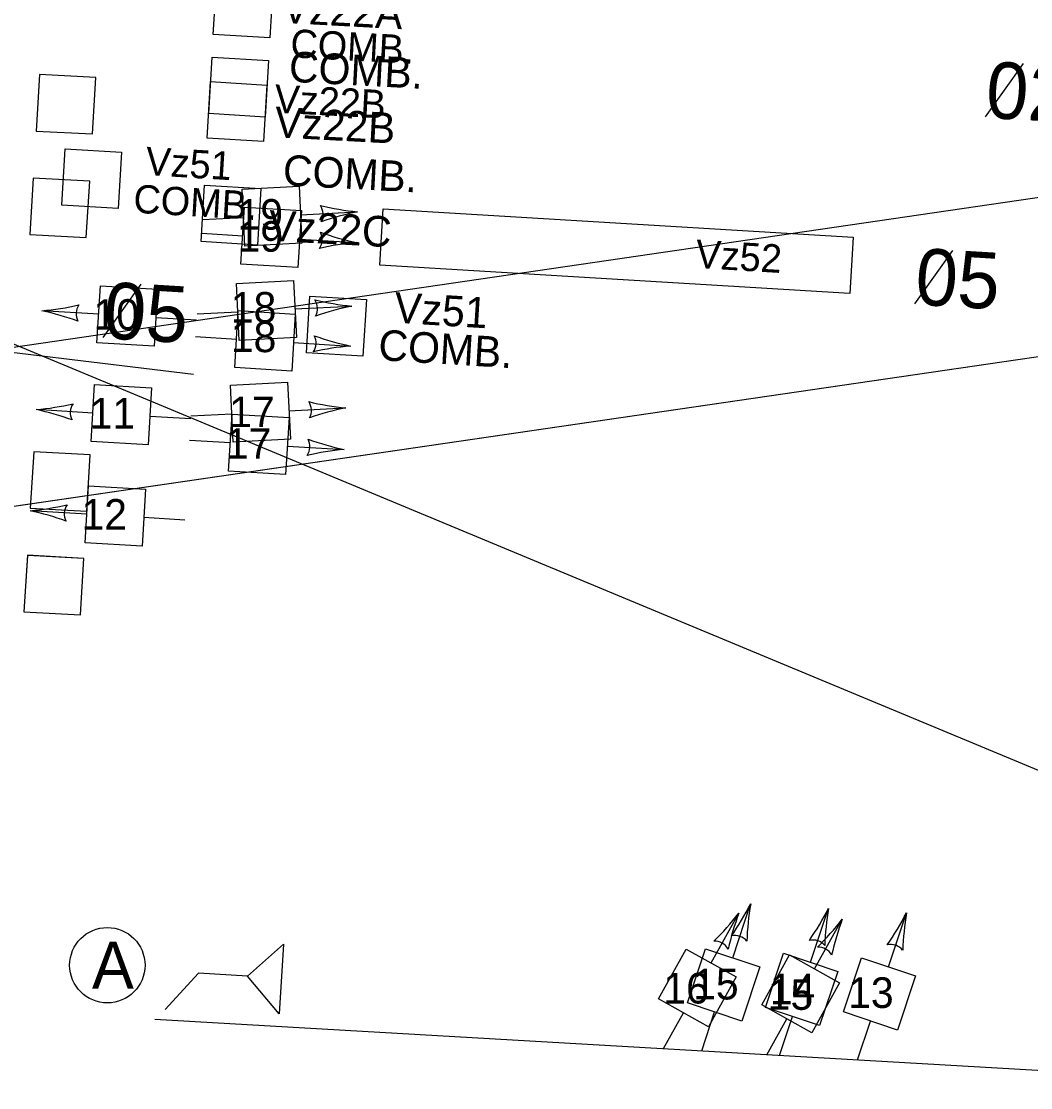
# Model space of a CAD drawing. Extents: x 647787 to 668496, y 640478 to 654412.
# Drawn here: x 661989.9 to 662097, y 647231.7 to 647344.8 of the extents above; entities that cross this region are included whole.
import ezdxf

# ---------------------------------------------------------------- set-up
doc = ezdxf.new("R2010")
doc.units = 0
for name, color, linetype in [('Default', 7, 'Continuous'), ('TEMP_DETECTION ZONE_Stage 2', 7, 'Continuous'), ('TEMP_DETECTION ZONE_STAGE 3', 7, 'Continuous'), ('TEMP_DETECTION_ZONE_STAGE 4', 7, 'Continuous'), ('TEMP_DETECTION_ZONE_STAGE 5', 7, 'Continuous'), ('TEMP_SIGNAL_HEAD_STAGE 2', 7, 'Continuous'), ('TEMP_SIGNAL_HEAD_Stage 3', 7, 'Continuous'), ('TEMP_SIGNAL_HEAD_STAGE4', 7, 'Continuous'), ('TEMP_SIGNAL_POLES_STAGE 1B', 7, 'Continuous'), ('TEMP_SIGNAL_POLES_STAGE 3', 7, 'Continuous'), ('TEMP_SIGNAL_POLES_STAGE 4', 7, 'Continuous'), ('TEXT_TEMP_SIGNAL_POLES_STAGE 2', 7, 'Continuous'), ('TEXT_TEMP_SIGNAL_POLES_STAGE 3', 7, 'Continuous'), ('TEXT_TEMP_SIGNAL_POLES_STAGE 4', 7, 'Continuous')]:
    doc.layers.add(name, color=color, linetype=linetype)

msp = doc.modelspace()

# ---------------------------------------------------------------- linework, layer by layer
at = {"layer": 'Default'}
for p, q in [((662092.24, 647334.7), (662096.28, 647340.36)), ((662084.74, 647314.88), (662088.79, 647320.54)), ((661998.56, 647311.3), (662002.6, 647316.96))]:
    msp.add_line(p, q, dxfattribs=at)
for points in [[(662193.11, 647333.04), (662139.14, 647248.2), (661974.83, 647316.48)], [(662136.44, 647331.77), (661882.02, 647294.61), (661114.4, 647320.89)], [(662008.15, 647307.38), (661891.05, 647321.5)], [(662008.15, 647307.38), (661891.05, 647321.5)], [(662008.15, 647307.38), (661891.05, 647321.5)], [(662108.29, 647310.77), (661853.87, 647273.61), (661086.25, 647299.89)], [(662108.29, 647310.77), (661888.55, 647278.68)], [(662108.29, 647310.77), (661888.55, 647278.68)]]:
    msp.add_lwpolyline(points, dxfattribs=at)
at = {"layer": 'TEMP_DETECTION ZONE_Stage 2'}
msp.add_lwpolyline([(662027.94, 647318.97), (662028.3, 647324.96), (662078.21, 647321.95), (662077.85, 647315.96)], close=True, dxfattribs=at)
at = {"layer": 'TEMP_DETECTION ZONE_STAGE 3'}
for points in [[(661991.81, 647339.19), (661991.45, 647333.2), (661997.44, 647332.89), (661997.8, 647338.88)], [(661991.81, 647339.19), (661991.45, 647333.2), (661997.44, 647332.89), (661997.8, 647338.88)], [(661991.81, 647339.19), (661991.45, 647333.2), (661997.44, 647332.89), (661997.8, 647338.88)], [(661991.81, 647339.19), (661991.45, 647333.2), (661997.44, 647332.89), (661997.8, 647338.88)], [(661991.15, 647328.21), (661990.78, 647322.22), (661996.78, 647321.91), (661997.14, 647327.9)], [(661991.15, 647328.21), (661990.78, 647322.22), (661996.78, 647321.91), (661997.14, 647327.9)], [(661991.15, 647328.21), (661990.78, 647322.22), (661996.78, 647321.91), (661997.14, 647327.9)], [(661991.15, 647328.21), (661990.79, 647322.22), (661996.78, 647321.91), (661997.14, 647327.9)]]:
    msp.add_lwpolyline(points, close=True, dxfattribs=at)
at = {"layer": 'TEMP_DETECTION_ZONE_STAGE 4'}
for points in [[(661991.19, 647299.15), (661990.82, 647293.17), (661996.82, 647292.85), (661997.18, 647298.84)], [(661991.19, 647299.15), (661990.82, 647293.17), (661996.82, 647292.85), (661997.18, 647298.84)], [(661991.19, 647299.15), (661990.82, 647293.17), (661996.82, 647292.85), (661997.18, 647298.84)], [(661991.19, 647299.16), (661990.83, 647293.17), (661996.82, 647292.86), (661997.18, 647298.84)], [(661990.53, 647288.18), (661990.16, 647282.19), (661996.16, 647281.88), (661996.52, 647287.86)], [(661990.52, 647288.17), (661990.16, 647282.19), (661996.15, 647281.87), (661996.52, 647287.86)], [(661990.52, 647288.17), (661990.16, 647282.19), (661996.15, 647281.87), (661996.52, 647287.86)], [(661990.52, 647288.17), (661990.16, 647282.19), (661996.15, 647281.87), (661996.52, 647287.86)]]:
    msp.add_lwpolyline(points, close=True, dxfattribs=at)
at = {"layer": 'TEMP_DETECTION_ZONE_STAGE 5'}
for points in [[(662015.77, 647334.69), (662009.78, 647335.05), (662010.14, 647341.04), (662016.13, 647340.68)], [(662000.16, 647324.97), (661994.17, 647325.33), (661994.53, 647331.32), (662000.52, 647330.96)]]:
    msp.add_lwpolyline(points, close=True, dxfattribs=at)
at = {"layer": 'TEMP_SIGNAL_HEAD_STAGE 2'}
for p, q in [((661998.1, 647313.76), (661992.07, 647314.12)), ((662008.49, 647313.13), (662004.15, 647313.39)), ((661997.47, 647303.28), (661991.44, 647303.64)), ((662007.86, 647302.65), (662003.53, 647302.91)), ((661996.84, 647292.55), (661990.81, 647292.91)), ((662007.23, 647291.92), (662002.89, 647292.18)), ((662008.69, 647243.84), (662005.16, 647239.99))]:
    msp.add_line(p, q, dxfattribs=at)
for points in [[(662004.33, 647316.42), (662003.97, 647310.37), (661997.91, 647310.73), (661998.28, 647316.79)], [(662003.71, 647305.94), (662003.34, 647299.89), (661997.29, 647300.25), (661997.66, 647306.3)], [(662003.07, 647295.21), (662002.7, 647289.15), (661996.65, 647289.52), (661997.02, 647295.57)]]:
    msp.add_lwpolyline(points, close=True, dxfattribs=at)
msp.add_lwpolyline([(662013.9, 647243.53), (662017.71, 647246.91), (662017.26, 647239.54), (662013.9, 647243.53), (662008.69, 647243.84)], dxfattribs=at)
for centre, radius, start, end in [((661989.42, 647343.48), 29.47, 275.1562, 282.8943), ((661985.91, 647285.3), 29.47, 70.2014, 77.9395), ((661997.32, 647313.81), 1.63, 144.7005, 208.3952), ((661988.8, 647332.99), 29.47, 275.1562, 282.8943), ((661985.29, 647274.82), 29.47, 70.2014, 77.9395), ((661996.7, 647303.32), 1.63, 144.7005, 208.3952), ((661988.16, 647322.26), 29.47, 275.1562, 282.8943), ((661996.06, 647292.59), 1.63, 144.7005, 208.3952), ((661984.65, 647264.09), 29.47, 70.2014, 77.9395)]:
    msp.add_arc(centre, radius, start, end, dxfattribs=at)
at = {"layer": 'TEMP_SIGNAL_HEAD_Stage 3'}
for p, q in [((662009.12, 647323.8), (662013.46, 647324.02)), ((662019.52, 647324.32), (662025.55, 647324.63)), ((662008.53, 647313.79), (662012.87, 647314.01)), ((662018.92, 647314.32), (662024.96, 647314.62)), ((662018.28, 647303.52), (662024.31, 647303.83)), ((662007.88, 647302.99), (662012.23, 647303.21)), ((662063.12, 647244.93), (662066.05, 647250.21)), ((662074.1, 647244.29), (662077.03, 647249.57)), ((662008.69, 647243.84), (662005.16, 647239.99)), ((662058.06, 647235.83), (662060.17, 647239.63)), ((662069.04, 647235.19), (662071.15, 647238.99))]:
    msp.add_line(p, q, dxfattribs=at)
for points in [[(662013.62, 647320.99), (662013.31, 647327.05), (662019.36, 647327.35), (662019.67, 647321.3)], [(662013.02, 647310.98), (662012.71, 647317.04), (662018.77, 647317.35), (662019.08, 647311.29)], [(662012.38, 647300.18), (662012.07, 647306.24), (662018.13, 647306.55), (662018.44, 647300.49)], [(662062.82, 647238.16), (662057.52, 647241.1), (662060.47, 647246.4), (662065.77, 647243.46)], [(662073.8, 647237.52), (662068.5, 647240.47), (662071.45, 647245.77), (662076.75, 647242.82)]]:
    msp.add_lwpolyline(points, close=True, dxfattribs=at)
msp.add_lwpolyline([(662013.9, 647243.53), (662017.71, 647246.91), (662017.26, 647239.54), (662013.9, 647243.53), (662008.69, 647243.84)], dxfattribs=at)
for centre, radius, start, end in [((662020.29, 647324.36), 1.63, 331.0639, 34.7585), ((662028.48, 647353.96), 29.47, 256.5647, 264.3029), ((662031.44, 647295.75), 29.47, 101.5195, 109.2576), ((662019.7, 647314.36), 1.63, 331.0639, 34.7585), ((662027.88, 647343.95), 29.47, 256.5647, 264.3029), ((662030.84, 647285.75), 29.47, 101.5195, 109.2576), ((662019.05, 647303.56), 1.63, 331.0639, 34.7585), ((662027.24, 647333.15), 29.47, 256.5647, 264.3029), ((662030.2, 647274.95), 29.47, 101.5195, 109.2576), ((662042.73, 647268.22), 29.47, 314.5817, 322.3198), ((662093.67, 647239.9), 29.47, 159.5365, 167.2746), ((662053.71, 647267.59), 29.47, 314.5817, 322.3198), ((662104.65, 647239.27), 29.47, 159.5365, 167.2746), ((662063.49, 647245.61), 1.63, 29.0808, 92.7755), ((662074.48, 647244.97), 1.63, 29.0808, 92.7755)]:
    msp.add_arc(centre, radius, start, end, dxfattribs=at)
at = {"layer": 'TEMP_SIGNAL_HEAD_STAGE4'}
for p, q in [((662009.04, 647322.37), (662013.38, 647322.1)), ((662019.43, 647321.74), (662025.46, 647321.37)), ((662008.38, 647311.39), (662012.72, 647311.12)), ((662018.78, 647310.76), (662024.8, 647310.39)), ((662007.73, 647300.4), (662012.07, 647300.14)), ((662018.12, 647299.78), (662024.15, 647299.41)), ((662065.4, 647245.47), (662067.31, 647251.2)), ((662073.67, 647244.99), (662075.59, 647250.72)), ((662081.95, 647244.51), (662083.86, 647250.24)), ((662008.69, 647243.84), (662005.16, 647239.99)), ((662062.11, 647235.6), (662063.48, 647239.72)), ((662070.38, 647235.12), (662071.75, 647239.24)), ((662078.65, 647234.64), (662080.03, 647238.76))]:
    msp.add_line(p, q, dxfattribs=at)
for points in [[(662013.19, 647319.08), (662013.56, 647325.13), (662019.61, 647324.76), (662019.25, 647318.71)], [(662012.54, 647308.1), (662012.91, 647314.15), (662018.96, 647313.78), (662018.59, 647307.73)], [(662011.89, 647297.12), (662012.25, 647303.17), (662018.3, 647302.8), (662017.94, 647296.75)], [(662066.36, 647238.76), (662060.6, 647240.68), (662062.52, 647246.43), (662068.28, 647244.51)], [(662074.63, 647238.28), (662068.88, 647240.2), (662070.8, 647245.95), (662076.55, 647244.03)], [(662082.9, 647237.8), (662077.15, 647239.72), (662079.07, 647245.47), (662084.82, 647243.55)]]:
    msp.add_lwpolyline(points, close=True, dxfattribs=at)
msp.add_lwpolyline([(662013.9, 647243.53), (662017.71, 647246.91), (662017.26, 647239.54), (662013.9, 647243.53), (662008.69, 647243.84)], dxfattribs=at)
for centre, radius, start, end in [((662020.2, 647321.69), 1.63, 324.6952, 28.3898), ((662031.62, 647350.19), 29.47, 250.1961, 257.9342), ((662028.1, 647292.02), 29.47, 95.1508, 102.8889), ((662019.55, 647310.71), 1.63, 324.6952, 28.3898), ((662027.45, 647281.04), 29.47, 95.1508, 102.8889), ((662030.97, 647339.21), 29.47, 250.1961, 257.9342), ((662018.89, 647299.73), 1.63, 324.6952, 28.3898), ((662030.31, 647328.23), 29.47, 250.1961, 257.9342), ((662026.8, 647270.06), 29.47, 95.1508, 102.8889), ((662041.07, 647264.61), 29.47, 325.2014, 332.9395), ((662096.35, 647246.16), 29.47, 170.1562, 177.8943), ((662049.34, 647264.13), 29.47, 325.2014, 332.9395), ((662104.62, 647245.68), 29.47, 170.1562, 177.8943), ((662057.61, 647263.65), 29.47, 325.2014, 332.9395), ((662112.9, 647245.2), 29.47, 170.1562, 177.8943), ((662065.65, 647246.2), 1.63, 39.7005, 103.3952), ((662073.92, 647245.73), 1.63, 39.7005, 103.3952), ((662082.19, 647245.25), 1.63, 39.7005, 103.3952)]:
    msp.add_arc(centre, radius, start, end, dxfattribs=at)
at = {"layer": 'TEMP_SIGNAL_POLES_STAGE 1B'}
for points in [[(662016.25, 647343.08), (662010.26, 647343.44), (662010.62, 647349.43), (662016.61, 647349.06)], [(662015.58, 647332.09), (662009.6, 647332.46), (662009.96, 647338.45), (662015.95, 647338.08)], [(662014.95, 647321.11), (662008.96, 647321.47), (662009.32, 647327.46), (662015.31, 647327.1)], [(662026.15, 647309.32), (662020.16, 647309.68), (662020.52, 647315.67), (662026.51, 647315.31)]]:
    msp.add_lwpolyline(points, close=True, dxfattribs=at)
at = {"layer": 'TEMP_SIGNAL_POLES_STAGE 3'}
msp.add_line((662004.07, 647238.96), (662129.5, 647231.69), dxfattribs=at)
at = {"layer": 'TEMP_SIGNAL_POLES_STAGE 4'}
msp.add_line((662004.07, 647238.96), (662129.5, 647231.69), dxfattribs=at)
at = {"layer": 'TEXT_TEMP_SIGNAL_POLES_STAGE 2'}
msp.add_circle((661999.01, 647244.68), 4, dxfattribs=at)
at = {"layer": 'TEXT_TEMP_SIGNAL_POLES_STAGE 3'}
msp.add_circle((661999.01, 647244.68), 4, dxfattribs=at)
at = {"layer": 'TEXT_TEMP_SIGNAL_POLES_STAGE 4'}
msp.add_circle((661999.01, 647244.68), 4, dxfattribs=at)

# ---------------------------------------------------------------- texts
at = {"layer": 'Default'}
for s, p in [('02', (662092.17, 647334.62)), ('05', (662084.68, 647314.8)), ('05', (661998.5, 647311.22))]:
    msp.add_text(s, height=6, rotation=356.6181, dxfattribs=at).set_placement(p)
at = {"layer": 'TEMP_DETECTION ZONE_Stage 2'}
msp.add_text('Vz52', height=3, rotation=356.5267, dxfattribs=at).set_placement((662061.4, 647318.69))
at = {"layer": 'TEMP_DETECTION_ZONE_STAGE 5'}
for s, rotation, p in [('COMB.', 356.9362, (662018.39, 647341.03)), ('Vz22B', 356.9362, (662016.69, 647335.16)), ('Vz51', 356.5267, (662003, 647328.54)), ('COMB.', 356.5267, (662001.71, 647324.55))]:
    msp.add_text(s, height=3, rotation=rotation, dxfattribs=at).set_placement(p)
at = {"layer": 'TEMP_SIGNAL_POLES_STAGE 1B'}
for s, rotation, p in [('Vz22A', 356.9362, (662017.5, 647344.69)), ('COMB.', 356.9362, (662018.23, 647338.44)), ('Vz22B', 356.9362, (662016.71, 647332.55)), ('COMB.', 356.9362, (662017.59, 647327.45)), ('Vz22C', 356.9362, (662016.07, 647321.57)), ('Vz51', 356.5267, (662029.4, 647312.87)), ('COMB.', 356.5267, (662027.72, 647308.9))]:
    msp.add_text(s, height=3.25, rotation=rotation, dxfattribs=at).set_placement(p)
at = {"layer": 'TEXT_TEMP_SIGNAL_POLES_STAGE 2'}
for s, height, p in [('10', 3.25, (661997.54, 647312.11)), ('11', 3.25, (661997.13, 647301.63)), ('12', 3.25, (661996.26, 647290.9)), ('A', 5, (661997.37, 647242.18))]:
    msp.add_text(s, height=height, dxfattribs=at).set_placement(p)
at = {"layer": 'TEXT_TEMP_SIGNAL_POLES_STAGE 3'}
for s, height, p in [('19', 3.25, (662012.83, 647322.73)), ('18', 3.25, (662012.12, 647312.87)), ('17', 3.25, (662011.95, 647301.78)), ('A', 5, (661997.37, 647242.18)), ('16', 3.25, (662058.04, 647240.62)), ('15', 3.25, (662069.12, 647239.95))]:
    msp.add_text(s, height=height, dxfattribs=at).set_placement(p)
at = {"layer": 'TEXT_TEMP_SIGNAL_POLES_STAGE 4'}
for s, height, p in [('19', 3.25, (662012.83, 647320.4)), ('18', 3.25, (662012.12, 647309.74)), ('17', 3.25, (662011.59, 647298.42)), ('A', 5, (661997.37, 647242.18)), ('15', 3.25, (662061.2, 647241.05)), ('14', 3.25, (662069.34, 647240.54)), ('13', 3.25, (662077.66, 647240.15))]:
    msp.add_text(s, height=height, dxfattribs=at).set_placement(p)

doc.saveas('drawing.dxf')
